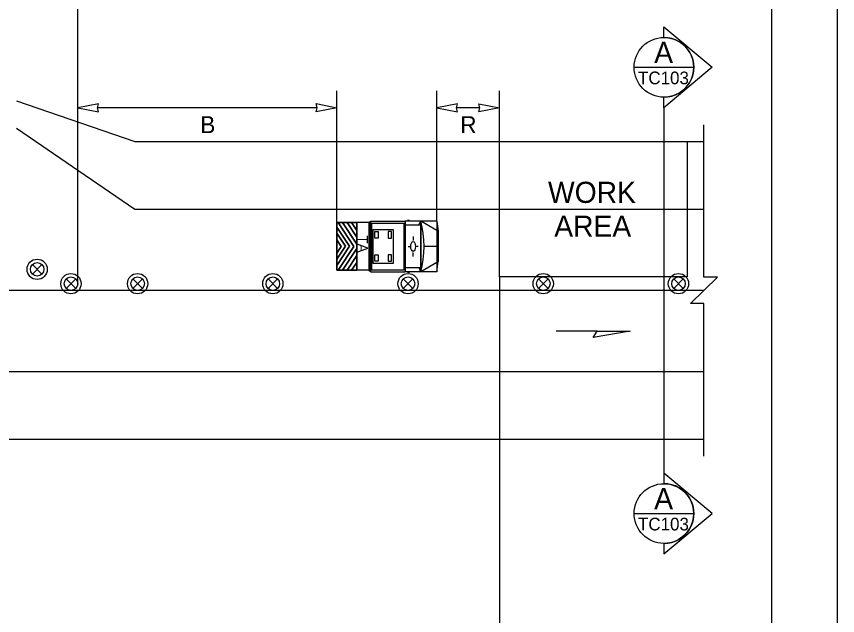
# Model space of a CAD drawing. Extents: x 99999 to 100116, y 99995 to 100013.
# Drawn here: x 100092.176 to 100096.062, y 100005.726 to 100008.56 of the extents above; entities that cross this region are included whole.
import ezdxf

# ---------------------------------------------------------------- set-up
doc = ezdxf.new("R2010")
doc.units = 0
for name, color, linetype in [('RD_MK_LineEdgeYellow', 7, 'Continuous'), ('RD_MK_LineLane', 7, 'Continuous'), ('SH_GI_PlotLimits', 7, 'Continuous'), ('SH_GI_SheetBorder', 7, 'Continuous'), ('SH_TI_WZSectionCut', 7, 'Continuous'), ('TR_WZ_TrafficSafetyDrum', 7, 'Continuous'), ('TR_WZ_TransportableAttenuator', 7, 'Continuous'), ('TR_WZ_WorkAreaLabel', 7, 'Continuous'), ('TR_WZ_WorkZoneDetails', 7, 'Continuous'), ('TR_WZ_WorkZoneTextCurrent', 7, 'Continuous')]:
    doc.layers.add(name, color=color, linetype=linetype)

msp = doc.modelspace()

# ---------------------------------------------------------------- linework, layer by layer
at = {"layer": 'RD_MK_LineEdgeYellow'}
for p, q in [((100092.1758, 100008.032), (100092.7368, 100007.648)), ((100092.7368, 100007.648), (100095.43, 100007.648)), ((100088.195, 100006.88), (100095.43, 100006.88))]:
    msp.add_line(p, q, dxfattribs=at)
at = {"layer": 'RD_MK_LineLane'}
msp.add_lwpolyline([(100095.43, 100007.264), (100088.195, 100007.264)], dxfattribs=at)
at = {"layer": 'SH_GI_PlotLimits'}
msp.add_lwpolyline([(100079.0625, 99999.6875), (100096.0625, 99999.6875), (100096.0625, 100010.6875), (100079.0625, 100010.6875)], close=True, dxfattribs=at)
at = {"layer": 'SH_GI_SheetBorder'}
msp.add_line((100095.75, 100010.375), (100095.75, 100000), dxfattribs=at)
at = {"layer": 'SH_TI_WZSectionCut'}
for p, q in [((100095.2407, 100008.4604), (100095.2407, 100008.5103)), ((100095.2407, 100008.5103), (100095.4688, 100008.3192)), ((100095.4688, 100008.3192), (100095.2407, 100008.128)), ((100095.2407, 100008.128), (100095.2407, 100008.1779)), ((100095.2407, 100008.128), (100095.2407, 100006.4)), ((100095.2407, 100006.4), (100095.2407, 100006.3501)), ((100095.4689, 100006.2089), (100095.2407, 100006.4)), ((100095.2407, 100006.0178), (100095.4689, 100006.2089)), ((100095.2407, 100006.0677), (100095.2407, 100006.0178))]:
    msp.add_line(p, q, dxfattribs=at)
for points in [[(100095.0995, 100008.3192), (100095.3819, 100008.3192)], [(100095.0995, 100006.2089), (100095.3819, 100006.2089)]]:
    msp.add_lwpolyline(points, dxfattribs=at)
for centre in [(100095.2407, 100008.3192), (100095.2407, 100006.2089)]:
    msp.add_circle(centre, 0.1412, dxfattribs=at)
for centre in [(100095.2407, 100008.3192), (100095.2407, 100006.2089)]:
    msp.add_arc(centre, 0.1412, 269.9978, 90.0022, dxfattribs=at)
at = {"layer": 'TR_WZ_TrafficSafetyDrum'}
for p, q in [((100092.2513, 100007.3413), (100092.2966, 100007.3866)), ((100092.2966, 100007.3413), (100092.2513, 100007.3866)), ((100092.4113, 100007.2734), (100092.4566, 100007.3186)), ((100092.4566, 100007.2734), (100092.4113, 100007.3186)), ((100092.7268, 100007.2734), (100092.772, 100007.3186)), ((100092.772, 100007.2734), (100092.7268, 100007.3186)), ((100093.3668, 100007.2734), (100093.412, 100007.3186)), ((100093.412, 100007.2734), (100093.3668, 100007.3186)), ((100094.0068, 100007.2734), (100094.052, 100007.3186)), ((100094.052, 100007.2734), (100094.0068, 100007.3186)), ((100094.6468, 100007.2734), (100094.692, 100007.3186)), ((100094.692, 100007.2734), (100094.6468, 100007.3186)), ((100095.2868, 100007.2734), (100095.332, 100007.3186)), ((100095.332, 100007.2734), (100095.2868, 100007.3186))]:
    msp.add_line(p, q, dxfattribs=at)
for centre, radius in [((100092.2739, 100007.3639), 0.048), ((100092.2739, 100007.3639), 0.048), ((100092.2739, 100007.3639), 0.032), ((100092.4339, 100007.296), 0.048), ((100092.4339, 100007.296), 0.048), ((100092.7494, 100007.296), 0.048), ((100092.7494, 100007.296), 0.048), ((100093.3894, 100007.296), 0.048), ((100093.3894, 100007.296), 0.048), ((100094.0294, 100007.296), 0.048), ((100094.0294, 100007.296), 0.048), ((100094.6694, 100007.296), 0.048), ((100094.6694, 100007.296), 0.048), ((100095.3094, 100007.296), 0.048), ((100095.3094, 100007.296), 0.048), ((100092.4339, 100007.296), 0.032), ((100092.7494, 100007.296), 0.032), ((100093.3894, 100007.296), 0.032), ((100094.0294, 100007.296), 0.032), ((100094.6694, 100007.296), 0.032), ((100095.3094, 100007.296), 0.032)]:
    msp.add_circle(centre, radius, dxfattribs=at)
at = {"layer": 'TR_WZ_TransportableAttenuator'}
for p, q in [((100093.7735, 100007.4722), (100093.6986, 100007.5849)), ((100093.6986, 100007.5849), (100093.719, 100007.5849)), ((100093.6986, 100007.5849), (100093.7735, 100007.4722)), ((100093.719, 100007.5849), (100093.6986, 100007.5849)), ((100093.719, 100007.5849), (100093.7868, 100007.4822)), ((100093.7868, 100007.4822), (100093.719, 100007.5849)), ((100093.7868, 100007.5154), (100093.7412, 100007.5849)), ((100093.7412, 100007.5849), (100093.7615, 100007.5849)), ((100093.7615, 100007.5849), (100093.7412, 100007.5849)), ((100093.7412, 100007.5849), (100093.7868, 100007.5154)), ((100093.7615, 100007.5849), (100093.7868, 100007.5467)), ((100093.7868, 100007.5467), (100093.7615, 100007.5849)), ((100093.7868, 100007.3596), (100093.7868, 100007.5849)), ((100093.8512, 100007.5849), (100093.7868, 100007.5849)), ((100093.8436, 100007.5808), (100093.8436, 100007.3633)), ((100093.8471, 100007.5881), (100093.8506, 100007.5881)), ((100093.8506, 100007.5881), (100093.8506, 100007.3559)), ((100093.8512, 100007.592), (100094.0137, 100007.592)), ((100093.8512, 100007.592), (100093.8512, 100007.352)), ((100093.8512, 100007.5845), (100093.8512, 100007.3596)), ((100093.8558, 100007.5825), (100093.8558, 100007.3616)), ((100093.8558, 100007.5825), (100094.0091, 100007.5825)), ((100094.0091, 100007.5825), (100094.0091, 100007.3616)), ((100094.0137, 100007.592), (100094.0137, 100007.352)), ((100094.0159, 100007.592), (100094.0159, 100007.352)), ((100094.1651, 100007.592), (100094.0159, 100007.592)), ((100094.0891, 100007.5734), (100094.0159, 100007.5734)), ((100094.0362, 100007.5954), (100094.0273, 100007.5954)), ((100094.0891, 100007.592), (100094.0796, 100007.5734)), ((100094.0891, 100007.592), (100094.0891, 100007.352)), ((100094.0905, 100007.592), (100094.0905, 100007.352)), ((100094.1651, 100007.5481), (100094.0905, 100007.592)), ((100094.1651, 100007.592), (100094.1651, 100007.352)), ((100094.1651, 100007.592), (100094.1724, 100007.5436)), ((100093.6924, 100007.5635), (100093.7525, 100007.4729)), ((100093.6924, 100007.5343), (100093.6924, 100007.5635)), ((100093.7525, 100007.4729), (100093.6924, 100007.5635)), ((100093.6924, 100007.5635), (100093.6924, 100007.5343)), ((100093.7332, 100007.4732), (100093.6924, 100007.5343)), ((100093.6924, 100007.5343), (100093.7332, 100007.4732)), ((100093.7868, 100007.5467), (100093.7868, 100007.5154)), ((100093.7868, 100007.5154), (100093.7868, 100007.5467)), ((100094.1724, 100007.5436), (100094.1724, 100007.4005)), ((100093.6924, 100007.5034), (100093.7133, 100007.4724)), ((100093.6924, 100007.441), (100093.6924, 100007.5034)), ((100093.7133, 100007.4724), (100093.6924, 100007.5034)), ((100093.6924, 100007.5034), (100093.6924, 100007.441)), ((100094.0533, 100007.5196), (100094.0533, 100007.5002)), ((100093.6924, 100007.4118), (100093.7332, 100007.4732)), ((100093.7332, 100007.4732), (100093.6924, 100007.4118)), ((100093.7525, 100007.4729), (100093.6924, 100007.3824)), ((100093.6924, 100007.3824), (100093.7525, 100007.4729)), ((100093.7133, 100007.4724), (100093.6924, 100007.441)), ((100093.6924, 100007.441), (100093.7133, 100007.4724)), ((100093.6986, 100007.3594), (100093.7735, 100007.4722)), ((100093.7735, 100007.4722), (100093.6986, 100007.3594)), ((100093.7868, 100007.4621), (100093.7186, 100007.3594)), ((100093.7186, 100007.3594), (100093.7868, 100007.4621)), ((100093.7868, 100007.4822), (100093.7868, 100007.4621)), ((100093.7868, 100007.4621), (100093.7868, 100007.4822)), ((100093.8436, 100007.4889), (100093.8506, 100007.4844)), ((100093.8436, 100007.4551), (100093.8506, 100007.4596)), ((100093.8455, 100007.472), (100093.8487, 100007.472)), ((100093.8471, 100007.4754), (100093.8471, 100007.4686)), ((100094.0295, 100007.4722), (100094.0394, 100007.4721)), ((100094.0422, 100007.4716), (100094.0422, 100007.4716)), ((100094.0771, 100007.4722), (100094.0672, 100007.4721)), ((100094.1651, 100007.472), (100094.1051, 100007.472)), ((100093.6924, 100007.3824), (100093.6924, 100007.4118)), ((100093.6924, 100007.4118), (100093.6924, 100007.3824)), ((100093.7406, 100007.3594), (100093.7868, 100007.4289)), ((100093.7868, 100007.4289), (100093.7406, 100007.3594)), ((100093.7868, 100007.4289), (100093.7868, 100007.3958)), ((100093.7868, 100007.3958), (100093.7868, 100007.4289)), ((100094.0533, 100007.4245), (100094.0533, 100007.4438)), ((100093.7868, 100007.3958), (100093.7622, 100007.3594)), ((100093.7622, 100007.3594), (100093.7868, 100007.3958)), ((100094.1651, 100007.3959), (100094.0905, 100007.352)), ((100094.1651, 100007.352), (100094.1724, 100007.4005)), ((100093.7186, 100007.3594), (100093.6986, 100007.3594)), ((100093.6986, 100007.3594), (100093.7186, 100007.3594)), ((100093.7622, 100007.3594), (100093.7406, 100007.3594)), ((100093.7406, 100007.3594), (100093.7622, 100007.3594)), ((100093.8512, 100007.3596), (100093.7868, 100007.3596)), ((100093.8471, 100007.3559), (100093.8506, 100007.3559)), ((100093.8512, 100007.352), (100094.0137, 100007.352)), ((100093.8558, 100007.3616), (100094.0091, 100007.3616)), ((100094.0891, 100007.3706), (100094.0159, 100007.3706)), ((100094.1651, 100007.352), (100094.0159, 100007.352)), ((100094.0362, 100007.3487), (100094.0273, 100007.3487)), ((100094.0813, 100007.3706), (100094.0891, 100007.352))]:
    msp.add_line(p, q, dxfattribs=at)
for points in [[(100093.7868, 100007.3594), (100093.6924, 100007.3594), (100093.6924, 100007.5849), (100093.7868, 100007.5849)], [(100093.8638, 100007.552), (100093.9598, 100007.552), (100093.9598, 100007.392), (100093.8638, 100007.392)], [(100093.8718, 100007.542), (100093.8878, 100007.542), (100093.8878, 100007.512), (100093.8718, 100007.512)], [(100093.9518, 100007.542), (100093.9358, 100007.542), (100093.9358, 100007.512), (100093.9518, 100007.512)], [(100093.8718, 100007.432), (100093.8878, 100007.432), (100093.8878, 100007.402), (100093.8718, 100007.402)], [(100093.9518, 100007.432), (100093.9358, 100007.432), (100093.9358, 100007.402), (100093.9518, 100007.402)]]:
    msp.add_lwpolyline(points, close=True, dxfattribs=at)
msp.add_lwpolyline([(100093.7868, 100007.5849), (100093.6924, 100007.5849), (100093.6924, 100007.3594), (100093.7868, 100007.3596)], dxfattribs=at)
for centre, major_axis, start_param, end_param in [((100093.8471, 100007.5807), (0, 0.00732), 6.283185, 7.853982), ((100093.9838, 100007.472), (0, 0.2519), 4.215852, 5.209111), ((100093.8471, 100007.3633), (0, -0.00732), 4.712389, 6.283185)]:
    msp.add_ellipse(centre, major_axis=major_axis, ratio=0.481608, start_param=start_param, end_param=end_param, dxfattribs=at)
for centre, major_axis in [((100094.0533, 100007.472), (0, -0.0231)), ((100093.8471, 100007.472), (0, -0.00338))]:
    msp.add_ellipse(centre, major_axis=major_axis, ratio=0.481608, dxfattribs=at)
at = {"layer": 'TR_WZ_WorkZoneDetails'}
for p, q in [((100092.4659, 100007.296), (100092.4659, 100009.294)), ((100093.6924, 100007.5849), (100093.6924, 100008.2083)), ((100094.1651, 100007.592), (100094.1651, 100008.208)), ((100094.4628, 100007.968), (100094.4628, 100008.208)), ((100092.1758, 100008.16), (100092.7368, 100007.968)), ((100093.5988, 100008.128), (100092.5596, 100008.128)), ((100094.3691, 100008.128), (100094.2588, 100008.128)), ((100092.7368, 100007.968), (100095.43, 100007.968)), ((100094.4628, 100007.328), (100094.4628, 100005.4763)), ((100094.9242, 100007.072), (100094.7313, 100007.072)), ((100088.195, 100006.56), (100095.43, 100006.56))]:
    msp.add_line(p, q, dxfattribs=at)
for points in [[(100092.4659, 100008.128), (100092.5642, 100008.1088), (100092.5596, 100008.128), (100092.5642, 100008.1473)], [(100093.6924, 100008.1283), (100093.5941, 100008.109), (100093.5987, 100008.1283), (100093.5941, 100008.1476)], [(100094.1651, 100008.128), (100094.2634, 100008.1088), (100094.2588, 100008.128), (100094.2634, 100008.1473)], [(100094.4628, 100008.128), (100094.3645, 100008.1088), (100094.3691, 100008.128), (100094.3645, 100008.1473)], [(100094.4628, 100007.328), (100094.4628, 100007.968), (100095.35, 100007.968), (100095.35, 100007.328)], [(100095.0815, 100007.072), (100094.9064, 100007.0412), (100094.9242, 100007.072)]]:
    msp.add_lwpolyline(points, close=True, dxfattribs=at)
msp.add_lwpolyline([(100095.43, 100006.48), (100095.43, 100007.2021), (100095.366, 100007.2021), (100095.494, 100007.326), (100095.43, 100007.326), (100095.43, 100008.048)], dxfattribs=at)

# ---------------------------------------------------------------- texts
at = {"layer": 'SH_TI_WZSectionCut'}
for s, height, rotation, p in [('A', 0.1, 0.01, (100095.1945, 100008.3398)), ('TC103', 0.06, 360, (100095.118, 100008.2392)), ('A', 0.1, 0.01, (100095.1945, 100006.2295)), ('TC103', 0.06, 360, (100095.118, 100006.1289))]:
    msp.add_text(s, height=height, rotation=rotation, dxfattribs=at).set_placement(p)
at = {"layer": 'TR_WZ_TransportableAttenuator'}
msp.add_text('TA', height=0.048, rotation=270, dxfattribs=at).set_placement((100093.7912, 100007.5246))
at = {"layer": 'TR_WZ_WorkAreaLabel'}
for s, p in [('WORK', (100094.6919, 100007.678)), ('AREA', (100094.7215, 100007.518))]:
    msp.add_text(s, height=0.1, dxfattribs=at).set_placement(p)
at = {"layer": 'TR_WZ_WorkZoneTextCurrent'}
for s, p in [('B', (100093.046, 100008.008)), ('R', (100094.2764, 100008.008))]:
    msp.add_text(s, height=0.08, dxfattribs=at).set_placement(p)

doc.saveas('drawing.dxf')
